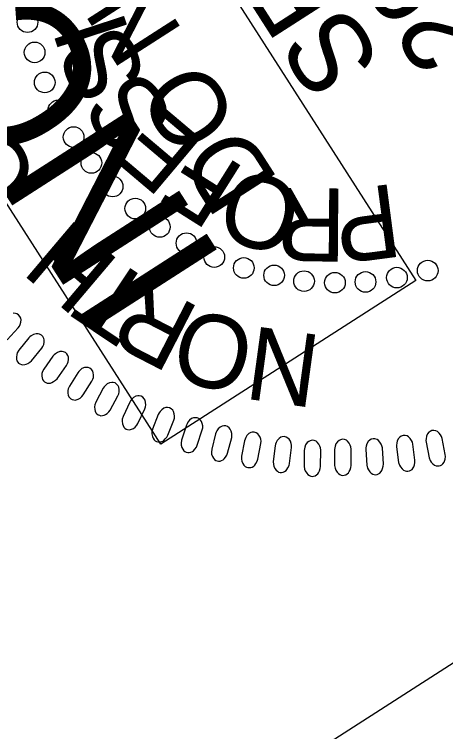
# Model space of a CAD drawing. Extents: x 476646 to 478477, y 498681 to 500689.
# Drawn here: x 476816 to 476849.5, y 499965.7 to 500021.3 of the extents above; entities that cross this region are included whole.
import ezdxf

# ---------------------------------------------------------------- set-up
doc = ezdxf.new("R2010")
doc.units = 0
for name, color, linetype in [('Sheet PE Seal Cell', 7, 'Continuous'), ('Sheet Plan CELL', 7, 'Continuous'), ('Sheet Sticker Incomplete CELL', 7, 'Continuous')]:
    doc.layers.add(name, color=color, linetype=linetype)

msp = doc.modelspace()

# ---------------------------------------------------------------- linework, layer by layer
at = {"layer": 'Sheet PE Seal Cell'}
msp.add_lwpolyline([(476815.469, 499996.036), (476816.33, 499996.952), (476816.429, 499997.091), (476816.491, 499997.224), (476816.534, 499997.402), (476816.548, 499997.58), (476816.53, 499997.705), (476816.457, 499997.856), (476816.361, 499997.972), (476816.224, 499998.045), (476816.114, 499998.08), (476815.952, 499998.093)], dxfattribs=at)
for points in [[(476817.151, 499996.177), (476816.374, 499995.228), (476816.263, 499995.035), (476816.215, 499994.894), (476816.194, 499994.691), (476816.2, 499994.545), (476816.236, 499994.412), (476816.292, 499994.315), (476816.366, 499994.228), (476816.465, 499994.172), (476816.576, 499994.12), (476816.695, 499994.1), (476816.839, 499994.11), (476816.936, 499994.135), (476817.083, 499994.207), (476817.243, 499994.308), (476817.362, 499994.418), (476818.164, 499995.385), (476818.254, 499995.53), (476818.308, 499995.667), (476818.34, 499995.847), (476818.342, 499996.026), (476818.317, 499996.149), (476818.233, 499996.295), (476818.131, 499996.405), (476817.99, 499996.469), (476817.877, 499996.497), (476817.716, 499996.5), (476817.516, 499996.445), (476817.35, 499996.349), (476817.244, 499996.267)], [(476819.026, 499994.765), (476818.31, 499993.769), (476818.212, 499993.569), (476818.173, 499993.426), (476818.165, 499993.222), (476818.18, 499993.077), (476818.224, 499992.947), (476818.286, 499992.853), (476818.366, 499992.772), (476818.468, 499992.722), (476818.583, 499992.676), (476818.702, 499992.664), (476818.846, 499992.683), (476818.941, 499992.714), (476819.083, 499992.796), (476819.236, 499992.907), (476819.347, 499993.023), (476820.087, 499994.039), (476820.168, 499994.189), (476820.213, 499994.329), (476820.234, 499994.511), (476820.224, 499994.689), (476820.192, 499994.811), (476820.1, 499994.951), (476819.99, 499995.055), (476819.845, 499995.109), (476819.731, 499995.13), (476819.57, 499995.124), (476819.373, 499995.056), (476819.214, 499994.949), (476819.114, 499994.862)], [(476820.955, 499993.487), (476820.302, 499992.448), (476820.218, 499992.243), (476820.187, 499992.096), (476820.191, 499991.893), (476820.216, 499991.748), (476820.269, 499991.621), (476820.336, 499991.532), (476820.42, 499991.455), (476820.526, 499991.412), (476820.643, 499991.374), (476820.763, 499991.369), (476820.905, 499991.398), (476820.998, 499991.434), (476821.135, 499991.524), (476821.281, 499991.645), (476821.385, 499991.768), (476822.059, 499992.828), (476822.131, 499992.984), (476822.167, 499993.126), (476822.175, 499993.308), (476822.155, 499993.487), (476822.115, 499993.605), (476822.014, 499993.74), (476821.898, 499993.836), (476821.75, 499993.882), (476821.635, 499993.895), (476821.475, 499993.879), (476821.283, 499993.799), (476821.131, 499993.682), (476821.036, 499993.588)], [(476822.933, 499992.281), (476822.347, 499991.203), (476822.275, 499990.992), (476822.254, 499990.845), (476822.272, 499990.642), (476822.305, 499990.5), (476822.365, 499990.376), (476822.438, 499990.291), (476822.527, 499990.22), (476822.634, 499990.184), (476822.754, 499990.153), (476822.875, 499990.155), (476823.014, 499990.193), (476823.105, 499990.235), (476823.236, 499990.334), (476823.374, 499990.463), (476823.47, 499990.592), (476824.077, 499991.693), (476824.138, 499991.852), (476824.165, 499991.997), (476824.163, 499992.179), (476824.131, 499992.356), (476824.084, 499992.472), (476823.974, 499992.6), (476823.853, 499992.689), (476823.702, 499992.725), (476823.587, 499992.732), (476823.427, 499992.705), (476823.241, 499992.612), (476823.096, 499992.487), (476823.008, 499992.388)], [(476824.984, 499991.2), (476824.467, 499990.087), (476824.408, 499989.872), (476824.396, 499989.724), (476824.426, 499989.523), (476824.468, 499989.382), (476824.536, 499989.263), (476824.614, 499989.182), (476824.708, 499989.117), (476824.818, 499989.087), (476824.939, 499989.065), (476825.059, 499989.075), (476825.196, 499989.121), (476825.284, 499989.168), (476825.408, 499989.275), (476825.537, 499989.413), (476825.626, 499989.548), (476826.162, 499990.685), (476826.213, 499990.848), (476826.231, 499990.994), (476826.217, 499991.176), (476826.175, 499991.349), (476826.12, 499991.463), (476826.003, 499991.583), (476825.876, 499991.664), (476825.723, 499991.692), (476825.607, 499991.69), (476825.45, 499991.654), (476825.27, 499991.55), (476825.133, 499991.415), (476825.052, 499991.311)], [(476827.204, 499990.247), (476826.758, 499989.104), (476826.713, 499988.886), (476826.71, 499988.737), (476826.753, 499988.538), (476826.804, 499988.401), (476826.88, 499988.286), (476826.963, 499988.21), (476827.06, 499988.151), (476827.171, 499988.129), (476827.293, 499988.113), (476827.412, 499988.131), (476827.547, 499988.186), (476827.631, 499988.238), (476827.749, 499988.354), (476827.87, 499988.499), (476827.948, 499988.639), (476828.413, 499989.807), (476828.453, 499989.973), (476828.463, 499990.12), (476828.437, 499990.301), (476828.383, 499990.471), (476828.322, 499990.582), (476828.197, 499990.694), (476828.065, 499990.767), (476827.912, 499990.784), (476827.796, 499990.776), (476827.641, 499990.73), (476827.468, 499990.615), (476827.34, 499990.472), (476827.265, 499990.362)], [(476829.389, 499989.414), (476829.015, 499988.246), (476828.984, 499988.026), (476828.991, 499987.877), (476829.046, 499987.681), (476829.105, 499987.547), (476829.187, 499987.437), (476829.275, 499987.367), (476829.376, 499987.314), (476829.489, 499987.299), (476829.612, 499987.291), (476829.73, 499987.315), (476829.86, 499987.379), (476829.941, 499987.437), (476830.051, 499987.559), (476830.163, 499987.711), (476830.233, 499987.857), (476830.623, 499989.051), (476830.653, 499989.22), (476830.653, 499989.366), (476830.616, 499989.545), (476830.552, 499989.712), (476830.483, 499989.818), (476830.352, 499989.923), (476830.215, 499989.987), (476830.061, 499989.994), (476829.946, 499989.98), (476829.795, 499989.923), (476829.63, 499989.798), (476829.511, 499989.647), (476829.443, 499989.533)], [(476831.649, 499988.741), (476831.35, 499987.551), (476831.332, 499987.329), (476831.349, 499987.181), (476831.416, 499986.989), (476831.483, 499986.859), (476831.573, 499986.754), (476831.665, 499986.69), (476831.768, 499986.643), (476831.882, 499986.635), (476832.006, 499986.635), (476832.121, 499986.667), (476832.247, 499986.739), (476832.325, 499986.801), (476832.427, 499986.93), (476832.528, 499987.089), (476832.589, 499987.238), (476832.903, 499988.456), (476832.923, 499988.625), (476832.913, 499988.771), (476832.865, 499988.948), (476832.791, 499989.112), (476832.717, 499989.213), (476832.579, 499989.309), (476832.438, 499989.365), (476832.284, 499989.362), (476832.17, 499989.34), (476832.022, 499989.274), (476831.865, 499989.139), (476831.756, 499988.981), (476831.695, 499988.863)], [(476833.901, 499988.21), (476833.677, 499987.005), (476833.674, 499986.782), (476833.7, 499986.635), (476833.779, 499986.447), (476833.854, 499986.322), (476833.95, 499986.223), (476834.045, 499986.165), (476834.152, 499986.125), (476834.266, 499986.124), (476834.389, 499986.132), (476834.503, 499986.171), (476834.624, 499986.25), (476834.697, 499986.318), (476834.791, 499986.452), (476834.883, 499986.618), (476834.934, 499986.77), (476835.171, 499988.005), (476835.18, 499988.175), (476835.162, 499988.321), (476835.102, 499988.494), (476835.018, 499988.652), (476834.937, 499988.748), (476834.793, 499988.836), (476834.65, 499988.883), (476834.496, 499988.87), (476834.384, 499988.841), (476834.24, 499988.766), (476834.092, 499988.621), (476833.993, 499988.457), (476833.94, 499988.335)], [(476847.996, 499988.1), (476848.232, 499986.896), (476848.311, 499986.688), (476848.388, 499986.561), (476848.531, 499986.416), (476848.648, 499986.327), (476848.773, 499986.27), (476848.884, 499986.252), (476848.998, 499986.253), (476849.103, 499986.294), (476849.215, 499986.347), (476849.306, 499986.425), (476849.39, 499986.543), (476849.434, 499986.633), (476849.471, 499986.793), (476849.494, 499986.98), (476849.486, 499987.141), (476849.253, 499988.376), (476849.198, 499988.538), (476849.127, 499988.667), (476849.009, 499988.806), (476848.872, 499988.921), (476848.761, 499988.981), (476848.595, 499989.01), (476848.445, 499989.001), (476848.306, 499988.933), (476848.213, 499988.863), (476848.107, 499988.742), (476848.023, 499988.552), (476847.991, 499988.363), (476847.986, 499988.229)], [(476836.277, 499987.817), (476836.128, 499986.6), (476836.139, 499986.377), (476836.174, 499986.233), (476836.265, 499986.05), (476836.348, 499985.93), (476836.45, 499985.838), (476836.548, 499985.785), (476836.658, 499985.752), (476836.771, 499985.758), (476836.894, 499985.774), (476837.005, 499985.82), (476837.121, 499985.906), (476837.19, 499985.978), (476837.275, 499986.119), (476837.356, 499986.29), (476837.397, 499986.445), (476837.557, 499987.692), (476837.555, 499987.863), (476837.527, 499988.007), (476837.457, 499988.176), (476837.363, 499988.328), (476837.275, 499988.419), (476837.127, 499988.497), (476836.982, 499988.535), (476836.828, 499988.514), (476836.718, 499988.477), (476836.58, 499988.393), (476836.441, 499988.24), (476836.352, 499988.07), (476836.307, 499987.944)], [(476838.533, 499987.453), (476838.528, 499986.227), (476838.565, 499986.007), (476838.617, 499985.867), (476838.728, 499985.697), (476838.825, 499985.587), (476838.937, 499985.508), (476839.041, 499985.467), (476839.154, 499985.447), (476839.266, 499985.466), (476839.386, 499985.497), (476839.491, 499985.555), (476839.595, 499985.655), (476839.656, 499985.734), (476839.723, 499985.884), (476839.784, 499986.064), (476839.807, 499986.222), (476839.818, 499987.479), (476839.797, 499987.649), (476839.752, 499987.788), (476839.663, 499987.948), (476839.551, 499988.088), (476839.454, 499988.168), (476839.297, 499988.229), (476839.148, 499988.249), (476838.998, 499988.21), (476838.894, 499988.16), (476838.766, 499988.061), (476838.646, 499987.892), (476838.578, 499987.713), (476838.548, 499987.583)], [(476840.891, 499987.523), (476840.897, 499986.297), (476840.935, 499986.078), (476840.987, 499985.938), (476841.1, 499985.769), (476841.198, 499985.66), (476841.31, 499985.58), (476841.415, 499985.541), (476841.528, 499985.522), (476841.64, 499985.543), (476841.759, 499985.573), (476841.864, 499985.633), (476841.968, 499985.733), (476842.028, 499985.813), (476842.094, 499985.964), (476842.153, 499986.143), (476842.174, 499986.302), (476842.176, 499987.559), (476842.153, 499987.729), (476842.108, 499987.869), (476842.017, 499988.027), (476841.904, 499988.166), (476841.807, 499988.246), (476841.649, 499988.305), (476841.5, 499988.324), (476841.351, 499988.284), (476841.246, 499988.233), (476841.119, 499988.133), (476841.001, 499987.963), (476840.934, 499987.783), (476840.905, 499987.653)], [(476843.32, 499987.533), (476843.402, 499986.309), (476843.454, 499986.093), (476843.516, 499985.956), (476843.639, 499985.795), (476843.744, 499985.692), (476843.86, 499985.62), (476843.967, 499985.588), (476844.081, 499985.575), (476844.191, 499985.603), (476844.309, 499985.64), (476844.409, 499985.707), (476844.506, 499985.814), (476844.561, 499985.897), (476844.618, 499986.051), (476844.666, 499986.234), (476844.677, 499986.395), (476844.6, 499987.649), (476844.567, 499987.817), (476844.512, 499987.953), (476844.412, 499988.106), (476844.291, 499988.238), (476844.188, 499988.311), (476844.028, 499988.36), (476843.877, 499988.37), (476843.731, 499988.32), (476843.63, 499988.264), (476843.509, 499988.155), (476843.402, 499987.978), (476843.347, 499987.795), (476843.326, 499987.663)], [(476845.706, 499987.747), (476845.865, 499986.53), (476845.93, 499986.317), (476846, 499986.185), (476846.134, 499986.032), (476846.244, 499985.936), (476846.366, 499985.872), (476846.475, 499985.846), (476846.589, 499985.84), (476846.697, 499985.875), (476846.812, 499985.92), (476846.908, 499985.992), (476846.998, 499986.105), (476847.047, 499986.192), (476847.095, 499986.349), (476847.131, 499986.535), (476847.133, 499986.696), (476846.977, 499987.944), (476846.932, 499988.108), (476846.869, 499988.241), (476846.76, 499988.387), (476846.63, 499988.511), (476846.524, 499988.578), (476846.361, 499988.617), (476846.21, 499988.617), (476846.067, 499988.558), (476845.969, 499988.495), (476845.856, 499988.38), (476845.76, 499988.196), (476845.717, 499988.01), (476845.704, 499987.877)]]:
    msp.add_lwpolyline(points, close=True, dxfattribs=at)
for centre in [(476817.052, 500020.666), (476817.606, 500018.325), (476818.392, 500015.992), (476819.446, 500013.83), (476820.635, 500011.755), (476822.013, 500009.753), (476823.659, 500007.924), (476825.418, 500006.214), (476827.325, 500004.788), (476829.392, 500003.531), (476831.549, 500002.454), (476833.843, 500001.608), (476848.125, 500001.4), (476836.197, 500001.036), (476845.729, 500000.857), (476838.52, 500000.586), (476840.916, 500000.467), (476843.292, 500000.524)]:
    msp.add_circle(centre, 0.801, dxfattribs=at)
at = {"layer": 'Sheet Plan CELL'}
msp.add_lwpolyline([(476782.554, 499927.632), (476814.18, 499947.922), (476760.156, 500032.132), (476854.856, 500092.886), (476908.852, 500008.673)], close=True, dxfattribs=at)
at = {"layer": 'Sheet Sticker Incomplete CELL'}
msp.add_lwpolyline([(476847.189, 500000.642), (476827.409, 499987.953), (476748.033, 500111.68), (476767.813, 500124.369)], close=True, dxfattribs=at)

# ---------------------------------------------------------------- texts
at = {"layer": 'Sheet PE Seal Cell'}
for s, height, rotation, p in [('29470', 6.2363, 122.6632, (476853.091, 500019.414)), ('SEAL', 6.2363, 122.6632, (476844.688, 500017.553)), ('I', 5.669, 108.0912, (476824.982, 500019.816)), ('S', 5.669, 116.031, (476826.503, 500016.276)), ('S', 5.669, 123.9708, (476828.673, 500013.081)), ('E', 5.669, 139.8504, (476830.975, 500011.27)), ('C', 5.669, 120.2695, (476818.167, 500008.173)), ('F', 5.669, 147.7902, (476834.1, 500009.248)), ('O', 5.669, 163.6698, (476838.738, 500007.831)), ('R', 5.669, 179.5494, (476841.807, 500007.763)), ('P', 5.669, 187.4892, (476845.547, 500008.159)), ('H', 5.669, 139.7376, (476824.345, 500002.031)), ('T', 5.669, 146.2269, (476827.248, 500000.117)), ('R', 5.669, 152.7163, (476830.602, 499998.442)), ('O', 5.669, 165.695, (476835.028, 499997.152)), ('N', 5.669, 172.1843, (476839.996, 499996.363))]:
    msp.add_text(s, height=height, rotation=rotation, dxfattribs=at).set_placement(p)
at = {"layer": 'Sheet Sticker Incomplete CELL'}
for s, height, p in [('INCOMPLETE PLANS', 11.52, (476832.508, 500001.857)), ('DO NOT USE FOR R/W ACQUISITION', 5.76, (476836.603, 500008.346))]:
    msp.add_text(s, height=height, rotation=122.6818, dxfattribs=at).set_placement(p)

doc.saveas('drawing.dxf')
